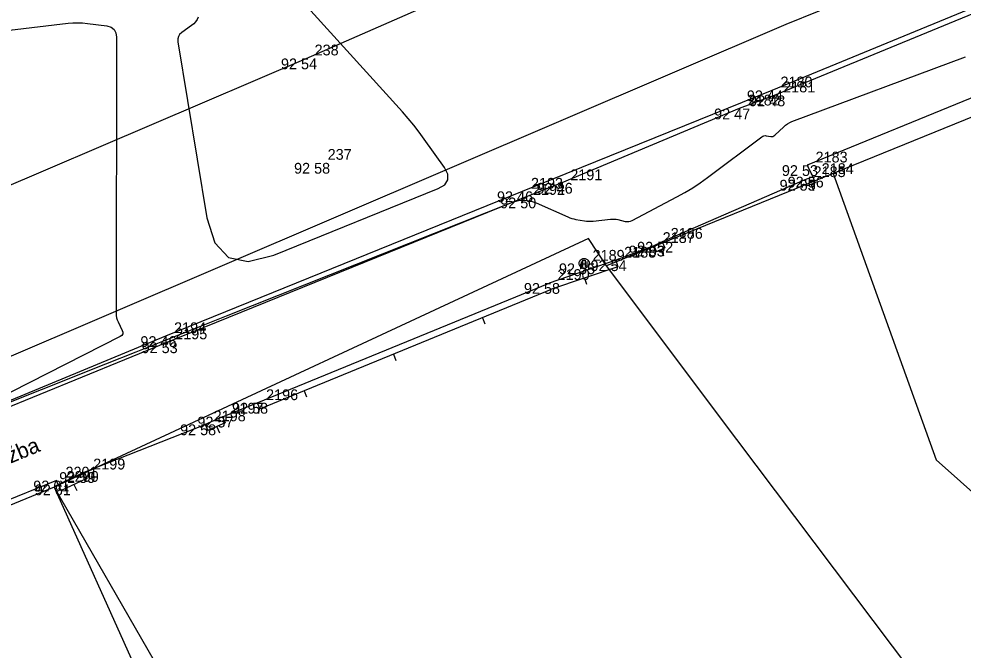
# Model space of a CAD drawing. Extents: x -711081 to -709338, y -1025122 to -1024092.
# Drawn here: x -710718.02 to -710693.5, y -1024924.43 to -1024908.04 of the extents above; entities that cross this region are included whole.
import ezdxf

# ---------------------------------------------------------------- set-up
doc = ezdxf.new("R2010")
doc.units = 0
for name, color, linetype in [('Ex_Minor Contours', 7, 'Continuous'), ('Z_betonova_konstrukce', 7, 'Continuous'), ('Z_body', 7, 'Continuous'), ('Z_body_cisla', 7, 'Continuous'), ('Z_body_vysky_redukovane', 7, 'Continuous'), ('Z_budova', 7, 'Continuous'), ('Z_katastr_hranice', 7, 'Continuous'), ('Z_katastr_vnitrni_kresba', 7, 'Continuous'), ('Z_komunikace', 7, 'Continuous'), ('Z_komunikace_osa', 7, 'Continuous'), ('Z_obruba', 7, 'Continuous'), ('Z_ploty', 7, 'Continuous'), ('Z_ploty_znacky', 7, 'Continuous'), ('Z_popisy', 7, 'Continuous'), ('Z_sloupy', 7, 'Continuous'), ('Z_vstupy', 7, 'Continuous')]:
    doc.layers.add(name, color=color, linetype=linetype)

# ---------------------------------------------------------------- blocks, each defined once
blk = doc.blocks.new('POINT_DISPLAY')
blk.add_line((0, 0), (0, 0))
blk = doc.blocks.new('Z210')
blk.add_line((0, 0), (0, 0.17))
blk = doc.blocks.new('Z601')
for p, q in [((-0.13, 0.03), (-0.1, 0.08)), ((-0.13, -0.03), (-0.13, 0.03)), ((-0.1, 0.08), (-0.08, 0.1)), ((-0.08, 0.1), (-0.03, 0.13)), ((-0.08, 0.05), (-0.08, -0.05)), ((-0.03, 0.13), (0.03, 0.13)), ((-0.03, -0.08), (-0.03, 0.08)), ((-0.03, 0.08), (0.03, 0.08)), ((0.03, 0.13), (0.08, 0.1)), ((0.03, 0.08), (0.03, -0.08)), ((0.08, 0.1), (0.1, 0.08)), ((0.08, -0.05), (0.08, 0.05)), ((0.1, 0.08), (0.13, 0.03)), ((0.13, 0.03), (0.13, -0.03)), ((-0.1, -0.08), (-0.13, -0.03)), ((-0.08, -0.1), (-0.1, -0.08)), ((-0.08, -0.05), (-0.03, -0.08)), ((-0.03, -0.13), (-0.08, -0.1)), ((0.03, -0.13), (-0.03, -0.13)), ((0.03, -0.08), (0.08, -0.05)), ((0.08, -0.1), (0.03, -0.13)), ((0.1, -0.08), (0.08, -0.1)), ((0.13, -0.03), (0.1, -0.08))]:
    blk.add_line(p, q)

msp = doc.modelspace()

# ---------------------------------------------------------------- linework, layer by layer
at = {"layer": 'Ex_Minor Contours'}
for points in [[(-710713.362, -1024907.993), (-710713.392, -1024908.058), (-710713.43, -1024908.117), (-710713.477, -1024908.169), (-710713.533, -1024908.214), (-710713.79, -1024908.396), (-710713.844, -1024908.444), (-710713.878, -1024908.5), (-710713.894, -1024908.564), (-710713.891, -1024908.636), (-710713.139, -1024913.206), (-710712.933, -1024913.857), (-710712.575, -1024914.236), (-710712.065, -1024914.344), (-710711.402, -1024914.18), (-710707.126, -1024912.444), (-710706.959, -1024912.346), (-710706.877, -1024912.224), (-710706.88, -1024912.076), (-710706.969, -1024911.904), (-710707.493, -1024911.165), (-710707.627, -1024910.982), (-710707.766, -1024910.804), (-710707.91, -1024910.629), (-710708.059, -1024910.459), (-710710.441, -1024907.835)], [(-710721.532, -1024908.727), (-710716.742, -1024908.154), (-710716.616, -1024908.143), (-710716.49, -1024908.14), (-710716.364, -1024908.145), (-710716.238, -1024908.158), (-710715.735, -1024908.225), (-710715.625, -1024908.256), (-710715.546, -1024908.314), (-710715.499, -1024908.4), (-710715.483, -1024908.513), (-710715.493, -1024915.681), (-710715.49, -1024915.741), (-710715.48, -1024915.799), (-710715.464, -1024915.855), (-710715.441, -1024915.91), (-710715.335, -1024916.128), (-710715.319, -1024916.179), (-710715.323, -1024916.223), (-710715.347, -1024916.26), (-710715.39, -1024916.291), (-710719.169, -1024918.208)], [(-710719.115, -1024918.328), (-710715.761, -1024916.995), (-710714.977, -1024916.683), (-710714.193, -1024916.372), (-710713.409, -1024916.06), (-710712.624, -1024915.749), (-710705.203, -1024912.804), (-710705.047, -1024912.758), (-710704.891, -1024912.745), (-710704.737, -1024912.765), (-710704.583, -1024912.817), (-710703.765, -1024913.183), (-710703.713, -1024913.204), (-710703.66, -1024913.222), (-710703.606, -1024913.237), (-710703.552, -1024913.248), (-710703.331, -1024913.286), (-710703.275, -1024913.294), (-710703.22, -1024913.297), (-710703.164, -1024913.297), (-710703.108, -1024913.293), (-710702.65, -1024913.242), (-710702.602, -1024913.239), (-710702.555, -1024913.24), (-710702.508, -1024913.245), (-710702.461, -1024913.254), (-710702.274, -1024913.298), (-710702.227, -1024913.305), (-710702.182, -1024913.303), (-710702.138, -1024913.294), (-710702.095, -1024913.275), (-710700.928, -1024912.665), (-710700.721, -1024912.551), (-710700.52, -1024912.43), (-710700.324, -1024912.3), (-710700.133, -1024912.163), (-710698.722, -1024911.101), (-710698.696, -1024911.085), (-710698.67, -1024911.076), (-710698.641, -1024911.072), (-710698.612, -1024911.074), (-710698.491, -1024911.095), (-710698.461, -1024911.097), (-710698.434, -1024911.092), (-710698.409, -1024911.081), (-710698.385, -1024911.063), (-710698.153, -1024910.842), (-710698.105, -1024910.801), (-710698.053, -1024910.765), (-710697.999, -1024910.734), (-710697.941, -1024910.709), (-710693.436, -1024909.026)]]:
    msp.add_lwpolyline(points, dxfattribs=at)
at = {"layer": 'Z_betonova_konstrukce'}
for p, q in [((-710685.39, -1024906.87), (-710697.55, -1024911.84)), ((-710697.55, -1024911.84), (-710697.4, -1024912.14))]:
    msp.add_line(p, q, dxfattribs=at)
at = {"layer": 'Z_budova'}
for p, q in [((-710717.04, -1024920.03), (-710725.67, -1024923.51)), ((-710717, -1024920.13), (-710717.04, -1024920.03)), ((-710717, -1024920.13), (-710716.93, -1024920.29))]:
    msp.add_line(p, q, dxfattribs=at)
at = {"layer": 'Z_katastr_hranice'}
for p, q in [((-710698.09, -1024908.18), (-710650.96, -1024888.93)), ((-710735.91, -1024924.36), (-710698.09, -1024908.18)), ((-710689.07, -1024908.88), (-710696.87, -1024912.06)), ((-710696.87, -1024912.06), (-710702.76, -1024914.45)), ((-710696.87, -1024912.06), (-710694.2, -1024919.49)), ((-710703.23, -1024913.74), (-710717.1, -1024920.2)), ((-710702.76, -1024914.45), (-710703.23, -1024913.74)), ((-710699.37, -1024918.96), (-710702.76, -1024914.45)), ((-710694.23, -1024925.79), (-710699.37, -1024918.96)), ((-710694.2, -1024919.49), (-710692.27, -1024921.21)), ((-710717.1, -1024920.2), (-710734.5, -1024927.33)), ((-710717.1, -1024920.2), (-710703.71, -1024943.42))]:
    msp.add_line(p, q, dxfattribs=at)
at = {"layer": 'Z_katastr_vnitrni_kresba'}
msp.add_line((-710717.1, -1024920.2), (-710712.55, -1024930.31), dxfattribs=at)
at = {"layer": 'Z_komunikace'}
for p, q in [((-710685.95, -1024904.75), (-710698.46, -1024909.9)), ((-710698.46, -1024909.9), (-710704.95, -1024912.52)), ((-710704.95, -1024912.52), (-710714.21, -1024916.28)), ((-710714.21, -1024916.28), (-710726.72, -1024921.45))]:
    msp.add_line(p, q, dxfattribs=at)
at = {"layer": 'Z_komunikace_osa'}
for p, q in [((-710710.56, -1024909.07), (-710697.96, -1024903.55)), ((-710721.27, -1024913.65), (-710710.56, -1024909.07))]:
    msp.add_line(p, q, dxfattribs=at)
at = {"layer": 'Z_obruba'}
for p, q in [((-710685.92, -1024904.9), (-710698.4, -1024910.03)), ((-710698.4, -1024910.03), (-710699.31, -1024910.37)), ((-710699.31, -1024910.37), (-710703.92, -1024912.3)), ((-710703.92, -1024912.3), (-710704.89, -1024912.68)), ((-710704.89, -1024912.68), (-710714.18, -1024916.44)), ((-710714.18, -1024916.44), (-710726.67, -1024921.55))]:
    msp.add_line(p, q, dxfattribs=at)
at = {"layer": 'Z_ploty'}
for p, q in [((-710697.4, -1024912.14), (-710697.61, -1024912.22)), ((-710697.61, -1024912.22), (-710697.55, -1024912.38)), ((-710697.4, -1024912.14), (-710697.34, -1024912.3)), ((-710697.34, -1024912.3), (-710697.55, -1024912.38)), ((-710701.31, -1024913.83), (-710701.53, -1024913.93)), ((-710701.53, -1024913.93), (-710701.46, -1024914.09)), ((-710701.24, -1024913.99), (-710701.46, -1024914.09)), ((-710701.31, -1024913.83), (-710701.24, -1024913.99)), ((-710702.52, -1024914.31), (-710704.25, -1024914.9)), ((-710702.46, -1024914.48), (-710704.19, -1024915.06)), ((-710702.52, -1024914.31), (-710702.46, -1024914.48)), ((-710711.83, -1024918.01), (-710704.25, -1024914.9)), ((-710711.76, -1024918.17), (-710704.19, -1024915.06)), ((-710711.83, -1024918.01), (-710711.76, -1024918.17)), ((-710712.73, -1024918.37), (-710713.18, -1024918.57)), ((-710712.73, -1024918.37), (-710712.66, -1024918.53)), ((-710713.18, -1024918.57), (-710713.11, -1024918.73)), ((-710712.66, -1024918.53), (-710713.11, -1024918.73)), ((-710717, -1024920.13), (-710716.32, -1024919.81)), ((-710716.32, -1024919.81), (-710716.25, -1024919.97)), ((-710716.93, -1024920.29), (-710716.25, -1024919.97))]:
    msp.add_line(p, q, dxfattribs=at)
at = {"layer": 'Z_vstupy'}
for p, q in [((-710697.61, -1024912.22), (-710701.31, -1024913.83)), ((-710701.53, -1024913.93), (-710702.52, -1024914.31)), ((-710712.73, -1024918.37), (-710711.83, -1024918.01)), ((-710716.32, -1024919.81), (-710713.18, -1024918.57))]:
    msp.add_line(p, q, dxfattribs=at)

# ---------------------------------------------------------------- block references
at = {"layer": 'Z_body'}
for p in [(-710710.56, -1024909.07), (-710698.46, -1024909.9), (-710698.4, -1024910.03), (-710699.31, -1024910.37), (-710710.22, -1024911.78), (-710697.55, -1024911.84), (-710697.61, -1024912.22), (-710697.4, -1024912.14), (-710704.95, -1024912.52), (-710703.92, -1024912.3), (-710704.89, -1024912.68), (-710701.53, -1024913.93), (-710701.31, -1024913.83), (-710703.34, -1024914.39), (-710702.52, -1024914.31), (-710704.25, -1024914.9), (-710714.21, -1024916.28), (-710714.18, -1024916.44), (-710711.83, -1024918.01), (-710712.73, -1024918.37), (-710713.18, -1024918.57), (-710716.32, -1024919.81), (-710717.04, -1024920.03), (-710717, -1024920.13)]:
    msp.add_blockref('POINT_DISPLAY', p, dxfattribs=at)
at = {"layer": 'Z_ploty_znacky'}
for p, rotation in [((-710697.44, -1024912.34), -159.10000000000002), ((-710701.35, -1024914.04), -155.60000000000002), ((-710703.33, -1024914.77), -161.20000000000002), ((-710705.98, -1024915.8), -157.7), ((-710708.29, -1024916.75), -157.7), ((-710710.61, -1024917.7), -157.7), ((-710712.88, -1024918.63), -156.00000000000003), ((-710716.59, -1024920.13), -154.80000000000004)]:
    msp.add_blockref('Z210', p, dxfattribs=dict(at, rotation=rotation))
at = {"layer": 'Z_sloupy'}
msp.add_blockref('Z601', (-710703.34, -1024914.39), dxfattribs=at)

# ---------------------------------------------------------------- texts
at = {"layer": 'Z_body_cisla'}
for s, p in [('238', (-710710.34, -1024908.99)), ('2180', (-710698.24, -1024909.82)), ('2181', (-710698.17, -1024909.95)), ('2182', (-710699.09, -1024910.29)), ('237', (-710710, -1024911.7)), ('2183', (-710697.33, -1024911.77)), ('2184', (-710697.17, -1024912.07)), ('2191', (-710703.7, -1024912.23)), ('2185', (-710697.38, -1024912.15)), ('2193', (-710704.72, -1024912.45)), ('2192', (-710704.67, -1024912.61)), ('2186', (-710701.09, -1024913.75)), ('2187', (-710701.3, -1024913.86)), ('2188', (-710702.3, -1024914.24)), ('2189', (-710703.12, -1024914.32)), ('2190', (-710704.03, -1024914.82)), ('2194', (-710713.99, -1024916.2)), ('2195', (-710713.96, -1024916.36)), ('2196', (-710711.6, -1024917.94)), ('2197', (-710712.5, -1024918.29)), ('2198', (-710712.96, -1024918.49)), ('2199', (-710716.09, -1024919.74)), ('2201', (-710716.81, -1024919.95)), ('2200', (-710716.78, -1024920.06))]:
    msp.add_text(s, height=0.28, dxfattribs=at).set_placement(p)
at = {"layer": 'Z_body_vysky_redukovane'}
for s, p in [('92 54', (-710711.213, -1024909.35)), ('92 44', (-710699.113, -1024910.18)), ('92 48', (-710699.053, -1024910.31)), ('92 47', (-710699.963, -1024910.65)), ('92 58', (-710710.873, -1024912.06)), ('92 53', (-710698.203, -1024912.12)), ('92 55', (-710698.263, -1024912.5)), ('92 56', (-710698.053, -1024912.42)), ('92 46', (-710705.603, -1024912.8)), ('92 46', (-710704.573, -1024912.58)), ('92 50', (-710705.52, -1024912.96)), ('92 53', (-710702.183, -1024914.21)), ('92 52', (-710701.963, -1024914.11)), ('92 55', (-710703.993, -1024914.67)), ('92 54', (-710703.173, -1024914.59)), ('92 58', (-710704.903, -1024915.18)), ('92 46', (-710714.863, -1024916.56)), ('92 53', (-710714.833, -1024916.72)), ('92 58', (-710712.483, -1024918.29)), ('92 57', (-710713.383, -1024918.65)), ('92 58', (-710713.833, -1024918.85)), ('92 59', (-710716.973, -1024920.09)), ('92 61', (-710717.647, -1024920.31)), ('92 61', (-710717.607, -1024920.41))]:
    msp.add_text(s, height=0.28, dxfattribs=at).set_placement(p)
at = {"layer": 'Z_popisy'}
msp.add_text('Chodník - zámk. dlažba', height=0.4, rotation=22.5, dxfattribs=at).set_placement((-710722.63, -1024921.41))

doc.saveas('drawing.dxf')
